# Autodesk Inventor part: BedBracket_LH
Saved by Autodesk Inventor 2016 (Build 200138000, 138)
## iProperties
Created: 2016-01
Part Number: BedBracket_LH
Material: Generic
Document SubType Name: Modeling
Designer: John
Density: 1 g/cm^3
Appearance: Default
Author: John
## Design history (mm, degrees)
feature "Base1"
body "Solid1"
